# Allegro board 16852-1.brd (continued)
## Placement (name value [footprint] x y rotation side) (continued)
PC5406  SC2D2U10V3KX-L-GP  [C603H36]  51.66 6.13 90 bottom
PC5407  SC2D2U10V3KX-L-GP  [C603H36]  167.89 42.78 90 top
PC5408  SC10U6D3V3MX-GP  [C603H38]  167.89 41.51 90 top
PC5409  SC10U6D3V3MX-GP  [C603H38]  167.26 53.07 90 top
PC5410  SC68P50V2JN-1GP  [C402H22]  161.8 51.55 270 top
PC5411  SC4700P50V2KX-1GP  [C402H22]  169.04 39.74 0 top
PC5412  SC10U6D3V3MX-GP  [C603H38]  167.26 51.8 90 top
PC8501  SCD01U50V2KX-1GP  [C402H22]  211.07 63.61 90 top
PC8502  SCD1U16V2KX-3GP  [C402H22]  208.84 54.98 180 bottom
PC8503  SC1KP50V2KX-1GP  [C402H22]  205.61 57.64 0 bottom
PC8506  SC330P50V2KX-3GP  [C402H22]  206.51 79.66 90 top
PC8507  SCD22U25V3KX-GP  [C603H40]  201.5 68.7 90 top
PC8508  SC1U10V2KX-1GP  [C402H22]  203.58 65.64 270 bottom
PC8509  SC1U10V2KX-1GP  [C402H22]  204.6 69.07 180 top
PC8510  SCD22U25V3KX-GP  [C603H40]  206.76 69.33 0 top
PC8511  SC1KP50V2KX-1GP  [C402H22]  210.57 54.98 180 bottom
PC8512  SC100P50V2JN-3GP  [C402H22]  211.07 66.41 90 top
PC8513  SC1KP50V2KX-1GP  [C402H22]  212.85 62.72 90 top
PC8514  SC180P50V2JN-1GP  [C402H22]  211.46 65.14 180 top
PC8515  SC330P50V2KX-3GP  [C402H22]  212.85 66.41 90 top
PC8516  SC330P50V2KX-3GP  [C402H22]  217.68 60.95 90 top
PC8517  SCD22U10V2KX-1GP  [C402H22]  211.33 57.64 0 top
PC8518  SCD22U10V2KX-1GP  [C402H22]  218.95 56.63 180 bottom
PC8519  SC10U25V5KX-GP  [C805H56]  211.07 93.97 90 bottom
PC8520  SC4D7U25V5KX-GP  [C805H54]  211.07 92.06 90 bottom
PC8521  SCD1U25V2KX-GP  [C402H22]  214.55 84.69 0 bottom
PC8522  SCD022U16V2KX-3GP  [C402H22]  213.74 58.79 180 top
PC8523  SCD1U25V2KX-GP  [C402H22]  214.63 58.79 180 top
PC8524  SC330P50V2KX-3GP  [C402H22]  211.06 62.8 270 top
PC8525  SCD1U25V2KX-GP  [C402H22]  216.92 60.11 90 top
PC8526  SC4D7U25V5KX-GP  [C805H54]  212.22 71.11 180 bottom
PC8527  SC4D7U25V5KX-GP  [C805H54]  210.31 71.11 180 bottom
PC8528  SC10U25V5KX-GP  [C805H56]  212.09 70.85 0 top
PC8529  SC10U25V5KX-GP  [C805H56]  210.19 70.85 0 top
PC8530  SCD1U25V2KX-GP  [C402H22]  215.11 75.45 180 bottom
PC8533  SC330P50V2KX-3GP  [C402H22]  206.51 80.63 90 top
PC8534  SC22U6D3V3MX-1-GP  [C603H40]  190.12 64.5 180 bottom
PC8535  SC22U6D3V3MX-1-GP  [C603H40]  191.77 64.5 0 top
PC8551  SC4D7U25V5KX-GP  [C805H54]  211.07 93.97 270 top
PC8552  SC10U25V5KX-GP  [C805H56]  211.07 92.06 270 top
PC8601  SCD1U16V2KX-3GP  [C402H22]  183.64 65.97 90 bottom
PC8602  SCD47U25V3KX-1GP  [C603H36]  177.22 63.41 90 bottom
PC8603  SCD1U16V2KX-3GP  [C402H22]  181.86 65.97 270 bottom
PC8604  SC22U6D3V5MX-2GP  [C805H58]  182.14 59.52 180 bottom
PC8605  SC22U6D3V5MX-2GP  [C805H58]  183.95 59.52 180 bottom
PC8607  SCD1U16V2KX-3GP  [C402H22]  174.45 61.22 270 bottom
PC8612  SCD22U10V2KX-1GP  [C402H22]  153.49 58.38 270 top
PC8621  SC10U6D3V3MX-GP  [C603H38]  179.6 57.77 270 bottom
PC8622  SC10U6D3V3MX-GP  [C603H38]  179.6 56.37 270 bottom
PC8623  SC1U10V2KX-1GP  [C402H22]  176.45 57.19 90 bottom
PC8624  SC22P50V2JN-4GP  [C402H22]  180.11 61.07 180 bottom
PC8625  SC22U6D3V3MX-1-GP  [C603H40]  169.04 63.23 90 bottom
PC8626  SC22U6D3V3MX-1-GP  [C603H40]  169.04 61.83 90 bottom
PC8634  SC1U10V2KX-1GP  [C402H22]  149.92 54.47 90 top
PC8635  SCD1U16V2KX-3GP  [C402H22]  148.59 54.91 180 top
PC8636  SCD1U16V2KX-3GP  [C402H22]  175.31 76.85 180 top
PC8651  SCD1U25V2KX-L-GP  [C402H22]  208.64 122.03 180 bottom
PC8652  SC10U25V5KX-L-GP  [C805H56]  209.04 124.55 0 bottom
PC8653  SC10U25V3MX-GP  [C603H40]  207.39 124.8 0 bottom
PC8654  SC2D2U10V3KX-L-GP  [C603H36]  200.53 117.16 180 bottom
PC8655  SC1U10V2KX-L1-GP  [C402H22]  202.54 117.1 180 bottom
PC8656  SCD1U25V2KX-L-GP  [C402H22]  202.59 124.85 180 bottom
PC8657  SC22U6D3V5MX-L3-GP  [C805H58]  193.29 125.84 180 top
PC8658  SC22U6D3V5MX-L3-GP  [C805H58]  195.12 125.84 180 top
PC8659  SC22U6D3V5MX-L3-GP  [C805H58]  192.79 120.25 0 top
PC8660  SC22U6D3V5MX-L3-GP  [C805H58]  194.59 120.25 0 top
PC8661  SC22U6D3V5MX-L3-GP  [C805H58]  199.26 126.99 270 bottom
PC8662  SC470P50V2KX-L-GP  [C402H22]  204.34 116.83 0 bottom
PD4301  P6SMB27A-GP  [DO214AAAKH97]  48.59 115.89 90 top
PD4302  LBAV99LT1G-1-GP  [SOT23-2D4-312H44]  33.53 62.34 0 top
PD4303  PESD24VS2UT-GP  [SOT-23-10H44]  28.96 69.2 90 top
PD4304  SMF18AT1G-GP  [SOD123FLAKH40]  231.52 28.69 270 top
PD4402  SD103AWS-2-GP  [SOD323AKH38]  235.71 24.24 270 top
PD4404  1N4148WS-7-F-GP  [SOD323AKH42]  233.12 6.92 0 top
PD4405  SD103AWS-2-GP  [SOD323AKH38]  231.01 24.24 90 top
PD8501  RB551VM-30TE-17-GP  [SOD323-2513AKH36]  205.99 54.34 270 top
PG4401  GAP-CLOSE-PWR-3-GP  [GAP-CLOSE-PWR-3]  239.57 13.12 0 top
PG4402  GAP-CLOSE-PWR-3-GP  [GAP-CLOSE-PWR-3]  66.08 104.58 180 top
PG4403  GAP-CLOSE-PWR-3-GP  [GAP-CLOSE-PWR-3]  66.05 103.1 180 top
PG4404  GAP-CLOSE-PWR-3-GP  [GAP-CLOSE-PWR-3]  223.14 18.02 90 top
PG4405  GAP-CLOSE-PWR-3-GP  [GAP-CLOSE-PWR-3]  221.11 18.02 90 top
PG4406  GAP-CLOSE-PWR-3-GP  [GAP-CLOSE-PWR-3]  224.16 18.02 90 top
PG4407  GAP-CLOSE-PWR-3-GP  [GAP-CLOSE-PWR-3]  222.12 18.02 90 top
PG4409  GAP-CLOSE-PWR-3-GP  [GAP-CLOSE-PWR-3]  239.93 18.02 0 top
PG4410  GAP-CLOSE-PWR-3-GP  [GAP-CLOSE-PWR-3]  239.93 19.04 0 top
PG4411  GAP-CLOSE-PWR-3-GP  [GAP-CLOSE-PWR-3]  241.48 11.97 270 top
PG4412  GAP-CLOSE-PWR-3-GP  [GAP-CLOSE-PWR-3]  225.58 32.37 90 top
PG4413  GAP-CLOSE-PWR-3-GP  [GAP-CLOSE-PWR-3]  227.05 32.37 90 top
PG4414  GAP-CLOSE-PWR-3-GP  [GAP-CLOSE-PWR-3]  239.62 14.13 0 top
PG4415  GAP-CLOSE-PWR-3-GP  [GAP-CLOSE-PWR-3]  239.65 15.15 0 top
PG4416  GAP-CLOSE-PWR-3-GP  [GAP-CLOSE-PWR-3]  237.64 21.83 270 top
PG4417  GAP-CLOSE-PWR-3-GP  [GAP-CLOSE-PWR-3]  236.6 21.83 90 top
PG4501  GAP-CLOSE-PWR-3-GP  [GAP-CLOSE-PWR-3]  27.94 45.83 270 top
PG4502  GAP-CLOSE-PWR-3-GP  [GAP-CLOSE-PWR-3]  28.96 45.83 270 top
PG4503  GAP-CLOSE-PWR-3-GP  [GAP-CLOSE-PWR-3]  26.92 45.83 270 top
PG4504  GAP-CLOSE-PWR-3-GP  [GAP-CLOSE-PWR-3]  42.8 41.39 180 top
PG4505  GAP-CLOSE-PWR-3-GP  [GAP-CLOSE-PWR-3]  42.8 42.4 180 top
PG4506  GAP-CLOSE-PWR-3-GP  [GAP-CLOSE-PWR-3]  29.46 46.92 0 bottom
PG4507  GAP-CLOSE-PWR-3-GP  [GAP-CLOSE-PWR-3]  56.38 40.73 180 top
PG4509  GAP-CLOSE-PWR-3-GP  [GAP-CLOSE-PWR-3]  27.46 29.4 0 bottom
PG4510  GAP-CLOSE-PWR-3-GP  [GAP-CLOSE-PWR-3]  45.72 40.12 270 top
PG4511  GAP-CLOSE-PWR-3-GP  [GAP-CLOSE-PWR-3]  43.69 40.12 270 top
PG4512  GAP-CLOSE-PWR-3-GP  [GAP-CLOSE-PWR-3]  44.7 40.12 270 top
PG4516  GAP-CLOSE-PWR-3-GP  [GAP-CLOSE-PWR-3]  29.18 29.63 270 top
PG4517  GAP-CLOSE-PWR-3-GP  [GAP-CLOSE-PWR-3]  28.27 29.63 270 top
PG4518  GAP-CLOSE-PWR-3-GP  [GAP-CLOSE-PWR-3]  27.36 29.63 270 top
PG4519  GAP-CLOSE-PWR-3-GP  [GAP-CLOSE-PWR-3]  25.53 29.63 270 top
PG4520  GAP-CLOSE-PWR-3-GP  [GAP-CLOSE-PWR-3]  26.44 29.63 270 top
PG4521  GAP-CLOSE-PWR-3-GP  [GAP-CLOSE-PWR-3]  30.1 29.63 270 top
PG4522  GAP-CLOSE-PWR-3-GP  [GAP-CLOSE-PWR-3]  25.91 45.83 270 top
PG4523  GAP-CLOSE-PWR-3-GP  [GAP-CLOSE-PWR-3]  24.61 29.63 270 top
PG4526  GAP-CLOSE-PWR-3-GP  [GAP-CLOSE-PWR-3]  24.89 45.83 270 top
PG4601  GAP-CLOSE-PWR-3-GP  [GAP-CLOSE-PWR-3]  148.59 116.7 0 top
PG4701  GAP-CLOSE-PWR-3-GP  [GAP-CLOSE-PWR-3]  122.05 124.7 90 top
PG4702  GAP-CLOSE-PWR-3-GP  [GAP-CLOSE-PWR-3]  121.13 124.7 90 top
PG4703  GAP-CLOSE-PWR-3-GP  [GAP-CLOSE-PWR-3]  120.19 124.7 90 top
PG4704  GAP-CLOSE-PWR-3-GP  [GAP-CLOSE-PWR-3]  119.28 124.7 90 top
PG4705  GAP-CLOSE-PWR-3-GP  [GAP-CLOSE-PWR-3]  118.26 124.7 90 top
PG4707  GAP-CLOSE-PWR-3-GP  [GAP-CLOSE-PWR-3]  123.95 112.13 90 bottom
PG4708  GAP-CLOSE-PWR-3-GP  [GAP-CLOSE-PWR-3]  123.95 109.84 270 bottom
PG4801  GAP-CLOSE-PWR-3-GP  [GAP-CLOSE-PWR-3]  107.44 123.3 270 bottom
PG4802  GAP-CLOSE-PWR-3-GP  [GAP-CLOSE-PWR-3]  108.46 123.3 270 bottom
PG4803  GAP-CLOSE-PWR-3-GP  [GAP-CLOSE-PWR-3]  109.47 123.3 270 bottom
PG4804  GAP-CLOSE-PWR-3-GP  [GAP-CLOSE-PWR-3]  106.43 123.3 270 top
PG4805  GAP-CLOSE-PWR-3-GP  [GAP-CLOSE-PWR-3]  107.44 123.3 270 top
PG4808  GAP-CLOSE-PWR-3-GP  [GAP-CLOSE-PWR-3]  113.59 108.19 90 bottom
PG4809  GAP-CLOSE-PWR-3-GP  [GAP-CLOSE-PWR-3]  113.59 106.41 270 bottom
PG5001  -  [GAP-CLOSE-PWR]  131.44 125.26 270 bottom
PG5002  -  [GAP-CLOSE-PWR]  132.46 125.26 270 bottom
PG5021  GAP-CLOSE-PWR-3-GP  [GAP-CLOSE-PWR-3]  135.42 110.94 90 bottom
PG5022  GAP-CLOSE-PWR-3-GP  [GAP-CLOSE-PWR-3]  135.42 108.65 270 bottom
PG5105  GAP-CLOSE-PWR-3-GP  [GAP-CLOSE-PWR-3]  58.32 70.45 0 top
PG5106  GAP-CLOSE-PWR-3-GP  [GAP-CLOSE-PWR-3]  67.35 54.06 270 top
PG5107  GAP-CLOSE-PWR-3-GP  [GAP-CLOSE-PWR-3]  68.36 54.06 270 top
PG5108  GAP-CLOSE-PWR-3-GP  [GAP-CLOSE-PWR-3]  69.38 54.06 270 top
PG5109  GAP-CLOSE-PWR-3-GP  [GAP-CLOSE-PWR-3]  71.41 54.06 270 top
PG5110  GAP-CLOSE-PWR-3-GP  [GAP-CLOSE-PWR-3]  58.32 71.46 0 top
PG5111  GAP-CLOSE-PWR-3-GP  [GAP-CLOSE-PWR-3]  70.39 54.06 270 top
PG5112  GAP-CLOSE-PWR-3-GP  [GAP-CLOSE-PWR-3]  58.57 62.28 90 top
PG5113  GAP-CLOSE-PWR-3-GP  [GAP-CLOSE-PWR-3]  66.55 56.12 0 top
PG5114  GAP-CLOSE-PWR-3-GP  [GAP-CLOSE-PWR-3]  58.2 67.05 0 top
PG5120  GAP-CLOSE-PWR-3-GP  [GAP-CLOSE-PWR-3]  59.18 52.49 270 top
PG5121  GAP-CLOSE-PWR-3-GP  [GAP-CLOSE-PWR-3]  60.2 52.49 270 top
PG5301  GAP-CLOSE-PWR-3-GP  [GAP-CLOSE-PWR-3]  38.62 18.56 270 top
PG5302  GAP-CLOSE-PWR-3-GP  [GAP-CLOSE-PWR-3]  37.71 18.56 270 top
PG5303  GAP-CLOSE-PWR-3-GP  [GAP-CLOSE-PWR-3]  34 18.56 270 top
PG5304  GAP-CLOSE-PWR-3-GP  [GAP-CLOSE-PWR-3]  36.79 18.56 270 top
PG5305  GAP-CLOSE-PWR-3-GP  [GAP-CLOSE-PWR-3]  35.88 18.56 270 top
PG5306  GAP-CLOSE-PWR-3-GP  [GAP-CLOSE-PWR-3]  34.97 18.56 270 top
PG5307  GAP-CLOSE-PWR-3-GP  [GAP-CLOSE-PWR-3]  47.12 35.55 270 top
PG5308  GAP-CLOSE-PWR-3-GP  [GAP-CLOSE-PWR-3]  49.15 35.55 270 top
PG5309  GAP-CLOSE-PWR-3-GP  [GAP-CLOSE-PWR-3]  48.13 35.55 270 top
PG5310  GAP-CLOSE-PWR-3-GP  [GAP-CLOSE-PWR-3]  41.4 19.8 180 top
PG5311  GAP-CLOSE-PWR-3-GP  [GAP-CLOSE-PWR-3]  39.54 18.56 270 top
PG5312  GAP-CLOSE-PWR-3-GP  [GAP-CLOSE-PWR-3]  40.48 18.56 270 top
PG5401  -  [GAP-CLOSE-PWR]  164.63 53.73 90 top
PG5402  -  [GAP-CLOSE-PWR]  165.63 53.73 90 top
PG5404  -  [GAP-CLOSE-PWR]  64.9 5.09 0 bottom
PG5405  -  [GAP-CLOSE-PWR]  64.9 6.11 0 bottom
PG8501  -  [GAP-CLOSE-PWR]  212.72 96.12 270 bottom
PG8502  -  [GAP-CLOSE-PWR]  211.71 96.12 270 bottom
PG8503  -  [GAP-CLOSE-PWR]  210.69 96.12 270 bottom
PG8504  -  [GAP-CLOSE-PWR]  212.72 96.12 270 top
PG8505  -  [GAP-CLOSE-PWR]  211.71 96.12 270 top
PG8506  -  [GAP-CLOSE-PWR]  210.69 96.12 270 top
PG8507  GAP-CLOSE-PWR-3-GP  [GAP-CLOSE-PWR-3]  204.61 75.07 0 bottom
PG8508  GAP-CLOSE-PWR-3-GP  [GAP-CLOSE-PWR-3]  202.13 75.04 180 bottom
PG8509  GAP-CLOSE-PWR-3-GP  [GAP-CLOSE-PWR-3]  204.47 82.74 0 bottom
PG8510  GAP-CLOSE-PWR-3-GP  [GAP-CLOSE-PWR-3]  202.1 82.71 180 bottom
PG8511  -  [GAP-CLOSE-PWR]  215.75 71.97 180 top
PG8512  -  [GAP-CLOSE-PWR]  215.75 72.98 180 top
PG8513  -  [GAP-CLOSE-PWR]  215.75 74 180 top
PG8514  -  [GAP-CLOSE-PWR]  215.77 71.99 180 bottom
PG8515  -  [GAP-CLOSE-PWR]  215.77 73.01 180 bottom
PG8516  -  [GAP-CLOSE-PWR]  215.77 74.03 180 bottom
PG8601  -  [GAP-CLOSE-PWR]  176.91 55.87 90 bottom
PG8602  -  [GAP-CLOSE-PWR]  177.93 55.87 90 bottom
PG8603  -  [GAP-CLOSE-PWR]  171.27 64.6 90 bottom
PG8604  -  [GAP-CLOSE-PWR]  170.18 64.6 90 bottom
PG8651  GAP-CLOSE-PWR-3-GP  [GAP-CLOSE-PWR-3]  209.55 122.03 90 bottom
PG8652  GAP-CLOSE-PWR-3-GP  [GAP-CLOSE-PWR-3]  210.57 122.03 90 bottom
PG8653  GAP-CLOSE-PWR-3-GP  [GAP-CLOSE-PWR-3]  196.72 120.76 180 bottom
PG8655  GAP-CLOSE-PWR-3-GP  [GAP-CLOSE-PWR-3]  209.04 117.46 180 bottom
PG8656  GAP-CLOSE-PWR-3-GP  [GAP-CLOSE-PWR-3]  192.56 119.82 270 bottom
PG8657  GAP-CLOSE-PWR-3-GP  [GAP-CLOSE-PWR-3]  191.77 122.08 180 bottom
PG8658  GAP-CLOSE-PWR-3-GP  [GAP-CLOSE-PWR-3]  191.77 121.12 180 bottom
PG8660  GAP-CLOSE-PWR-3-GP  [GAP-CLOSE-PWR-3]  191.74 124.27 180 bottom
PL4401  COIL-4D7UH-33-GP  [L7066-1830-UH119]  222.5 33.01 0 bottom
PL4501  IND-2D2UH-46-GP-U1  [L7066-1830-UH119]  33.94 43.36 270 bottom
PL4502  IND-2D2UH-46-GP-U1  [L7066-1830-UH119]  33.78 33.77 90 bottom
PL4701  COIL-D15UH-2-GP  [L7366-1930H158]  123.95 110.98 180 bottom
PL4801  COIL-D15UH-2-GP  [L7366-1930H158]  113.03 107.33 180 bottom
PL5001  IND-D47UH-22-GP-U  [L7066-1830-UH119]  135.42 109.79 180 bottom
PL5101  COIL-1UH-34-GP-U1  [L7066-1830-UH119]  70 64.1 180 bottom
PL5301  COIL-1UH-34-GP-U1  [L7066-1830-UH119]  34.58 25.37 180 bottom
PL8501  IND-D33UH-7-GP-U  [L7066-1830-UH119]  203.33 74.97 90 bottom
PL8502  IND-D33UH-7-GP-U  [L7066-1830-UH119]  203.33 82.71 90 bottom
PL8601  IND-1UH-300-GP  [L2520-D620H48]  171.22 58.89 90 bottom
PL8651  COIL-1UH-34-GP-U1  [L7066-1830-UH119]  197.61 122.16 90 bottom
PQ4301  DMN5L06K-7-GP  [SOT23DGS2D4H48]  32.89 66.41 0 top
PQ4302  LMBT3904LT1G-GP  [SOT23CBE2D4H44]  29.72 62.6 180 top
PQ4304  LMUN5212T1G-GP  [SOT323CBE2D2H40]  57.96 103.41 0 top
PQ4305  LTA024EUBFS8TL-GP  [SC70-2D2-312H44]  61.11 103.39 0 top
PQ4306  2N7002KDW-GP  [SOT-363H44]  53.39 102.37 0 top
PQ4402  2N7002KDW-GP  [SOT-363H44]  74.75 108.54 180 top
PQ4403  2N7002K-2-GP  [SOT23DGS2D4H44]  239.65 25.89 90 top
PQ4405  2N7002KDW-GP  [SOT-363H44]  245.03 14.51 180 top
PQ4408  LMBT3906LT1G-1-GP  [SOT23CBE2D4H44]  236.14 6.67 0 top
PQ8501  2N7002KDW-GP  [SOT-363H44]  209.8 52.94 270 top
PQ8604  2N7002KDW-GP  [SOT-363H44]  179.96 63.74 180 bottom
PQ8607  DMP2130L-7-GP  [SOT23DGS2D4H48]  148.15 52.16 180 top
PQ8608  2N7002K-2-GP  [SOT23DGS2D4H44]  152.58 55.94 180 top
PQ8609  PJA3419-GP  [SOT23DGS2D4H44]  183.26 63.49 0 bottom
PR4302  15KR2F-GP  [R402H16]  29.97 65.01 270 top
PR4303  10KR2J-3-GP  [R402H16]  29.07 60.29 90 top
PR4304  2K2R2J-2-GP  [R402H16]  35.94 62.34 180 top
PR4305  33R2J-2-GP  [R402H16]  35.18 64.63 0 top
PR4306  33R2J-2-GP  [R402H16]  32.51 68.82 90 top
PR4307  240KR3-GP  [R603H22]  60.45 107.17 0 top
PR4308  47KR3J-L-GP  [R603H22]  62.46 106.03 90 top
PR4309  100KR2J-1-GP  [R402H16]  30.48 66.41 0 top
PR4312  100KR2J-1-GP  [R402H16]  50.33 101.09 90 top
PR4313  100KR2J-1-GP  [R402H16]  50.3 100.17 270 top
PR4314  3K3R6J-GP  [R1206H28]  49.15 112.51 270 top
PR4317  0R0603-PAD-1-GP-U  [0R0603-PAD-U]  30.48 71.99 90 bottom
PR4402  D01R3721F-GP-U  [R3720H40]  68.57 103.84 0 top
PR4403  100KR2J-1-GP  [R402H16]  71.6 105.4 180 top
PR4404  0R2J-2-GP  [R402H16]  231.91 11.34 90 top
PR4405  3KR5J-GP  [R805H24]  72.21 109.81 0 top
PR4406  10KR2F-2-GP  [R402H16]  72.9 105.78 270 top
PR4407  10R2J-2-GP  [R402H14]  229.29 14.72 90 top
PR4408  309KR2F-GP  [R402H16]  239.7 11.59 180 top
PR4409  47KR2F-GP  [R402H16]  238.07 11.59 0 top
PR4410  4K02R2F-GP  [R402H16]  234.37 11.09 180 top
PR4411  3K3R2J-3-GP  [R402H16]  241.2 17.64 180 top
PR4412  3K3R2J-3-GP  [R402H16]  241.2 19.44 0 top
PR4413  100KR2F-L1-GP  [R402H16]  244.4 12.1 90 top
PR4414  10R2F-L-GP  [R402H14]  234.72 21.8 90 top
PR4415  D01R3721F-GP-U  [R3720H40]  226.31 34.78 90 top
PR4416  0R0402-PAD-2-GP  [0R0402-PAD-1]  235.26 11.09 180 top
PR4417  10R2F-L-GP  [R402H14]  232.33 21.55 180 top
PR4418  0R0402-PAD-2-GP  [0R0402-PAD-1]  239.85 16.7 270 top
PR4419  10R2F-L-GP  [R402H14]  233.22 21.55 180 top
PR4420  100KR2J-1-GP  [R402H16]  230.89 21.12 90 top
PR4421  59KR2F-GP  [R402H16]  238.61 20.99 0 top
PR4422  20KR3J-1-GP  [R603H22]  236.85 26.78 180 top
PR4423  59KR2F-GP  [R402H16]  230.89 21.96 270 top
PR4424  10KR2F-2-GP  [R402H16]  239.5 20.99 180 top
PR4425  30KR2F-GP  [R402H16]  241.94 15.15 90 top
PR4430  470KR2F-GP  [R402H16]  237.74 32.24 0 bottom
PR4431  100KR2J-1-GP  [R402H16]  241.22 9.94 90 top
PR4432  120KR2J-GP  [R402H16]  236.65 12.36 90 top
PR4433  1MR2J-1-GP  [R402H16]  241.22 10.83 270 top
PR4435  100KR2J-1-GP  [R402H16]  236.14 11.09 180 top
PR4450  10KR2F-2-GP  [R402H16]  246.18 12.1 90 top
PR4451  680KR2F-GP  [R402H16]  238.71 9.38 0 top
PR4455  0R0402-PAD-2-GP  [0R0402-PAD-1]  242.65 16.19 270 top
PR4458  0R0402-PAD-2-GP  [0R0402-PAD-1]  231.57 6.39 0 top
PR4462  0R0402-PAD-2-GP  [0R0402-PAD-1]  237.41 9.82 90 top
PR4463  0R2J-2-GP  [R402H16]  237.03 11.09 180 top
PR4502  0R0402-PAD-1-GP  [0R0402-PAD]  53.92 47.43 0 top
PR4503  1D5R3F-GP  [R603H22]  49.8 47.82 0 top
PR4505  165KR2F-L-GP  [R402H16]  56.01 46.9 90 top
PR4506  0R2J-2-GP  [R402H16]  57.81 45.64 0 top
PR4507  0R0402-PAD-1-GP  [0R0402-PAD]  53.85 38.54 0 top
PR4508  100KR2J-1-GP  [R402H16]  52.27 47.52 0 top
PR4509  1D5R3F-GP  [R603H22]  50.62 38.42 0 top
PR4510  130KR2F-L-GP  [R402H16]  55.24 38.59 0 top
PR4512  0R2J-2-GP  [R402H16]  58.22 38.57 270 top
PR4514  15KR2F-GP  [R402H16]  58.22 39.41 270 top
PR4515  10KR2F-2-GP  [R402H16]  56.52 39.86 90 top
PR4516  6K65R2F-GP  [R402H16]  56.05 45.03 270 top
PR4517  10KR2F-2-GP  [R402H16]  56.03 45.95 90 top
PR4601  1KR2F-3-GP  [R402H16]  142.11 109.28 270 bottom
PR4602  1K5R2F-2-GP  [R402H16]  154.38 114.39 270 bottom
PR4603  1KR2F-3-GP  [R402H16]  144.7 107.65 0 bottom
PR4604  0R0402-PAD-2-GP  [0R0402-PAD-1]  154.81 112.43 90 bottom
PR4605  825R2F-GP  [R402H16]  152.27 112.51 90 bottom
PR4606  NTC-100K-11-GP-U  [NTC-402H24-U]  139.83 108.7 0 bottom
PR4607  0R0402-PAD-2-GP  [0R0402-PAD-1]  154.81 111.62 90 bottom
PR4608  2K94R2F-GP  [R402H16]  152.27 110.73 90 bottom
PR4609  14K3R2F-GP  [R402H16]  154.31 115.78 180 bottom
PR4611  34KR2F-GP  [R402H16]  151.97 114.23 270 bottom
PR4612  8K06R3F-AS-GP  [R603H22]  153.21 116.39 180 bottom
PR4613  115KR2F-GP  [R402H16]  149.48 114.67 270 top
PR4614  10KR2F-2-GP  [R402H16]  152.45 120.05 90 bottom
PR4616  2K49R2F-GP  [R402H16]  153.54 110.22 180 bottom
PR4617  0R0402-PAD-2-GP  [0R0402-PAD-1]  152.78 110.22 180 top
PR4618  0R0402-PAD-2-GP  [0R0402-PAD-1]  152.78 107.81 270 top
PR4619  1KR2F-3-GP  [R402H16]  148.72 108.52 90 bottom
PR4621  45D3R2F-L-GP  [R402H16]  150.19 121.88 180 bottom
PR4622  75R2F-2-GP  [R402H16]  149.35 121.91 0 top
PR4623  100R2F-L1-GP-U  [R402H14]  148.51 121.93 180 bottom
PR4624  1KR2F-3-GP  [R402H16]  148.46 121.91 0 top
PR4625  37D4R2F-GP  [R402H16]  148.16 106.83 0 top
PR4626  1KR2F-3-GP  [R402H16]  147.65 108.1 270 top
PR4627  8K06R3F-AS-GP  [R603H22]  147.44 122.59 0 bottom
PR4628  95K3R2F-GP  [R402H16]  146.94 116.95 0 top
PR4629  14KR2F-GP  [R402H16]  146.3 122.34 0 bottom
PR4630  0R0402-PAD-2-GP  [0R0402-PAD-1]  151.13 119.62 0 bottom
PR4631  4K75R2F-1-GP  [R402H16]  146.89 106.32 270 top
PR4632  24K9R2F-L-GP  [R402H16]  147.07 111.11 0 top
PR4633  NTC-100K-11-GP-U  [NTC-402H24-U]  128.4 112.63 0 bottom
PR4634  NTC-220K-GP-U  [NTC-402H22-U]  118.24 111.41 180 bottom
PR4635  49K9R2F-L-GP  [R402H16]  145.09 119.33 180 top
PR4636  2K49R2F-GP  [R402H16]  144.66 120.72 90 top
PR4637  57K6R3F-2-GP  [R603H22]  144.02 104.86 270 bottom
PR4638  200KR2F-L-GP  [R402H16]  145.62 105.94 0 bottom
PR4639  75KR2F-GP  [R402H16]  146.89 106.35 270 bottom
PR4640  12K4R2F-GP  [R402H16]  147.65 107.2 270 bottom
PR4644  422R2F-2-GP  [R402H16]  144.02 119.62 0 bottom
PR4645  0R0402-PAD-2-GP  [0R0402-PAD-1]  143 120.25 180 bottom
PR4646  10R2F-L-GP  [R402H14]  144.46 106.89 0 top
PR4647  3K83R2F-GP  [R402H16]  142.22 117.75 0 bottom
PR4648  0R0402-PAD-2-GP  [0R0402-PAD-1]  142.19 120.25 180 bottom
PR4649  2K49R2F-GP  [R402H16]  141.4 117.75 0 bottom
PR4650  0R0402-PAD-2-GP  [0R0402-PAD-1]  140.44 112.96 270 bottom
PR4651  4K87R2F-GP  [R402H16]  143.62 106.9 180 top
PR4652  21K5R2F-GP  [R402H16]  140.06 111.69 180 bottom
PR4653  NTC-100K-11-GP-U  [NTC-402H24-U]  128.27 120.89 270 bottom
PR4655  0R0402-PAD-2-GP  [0R0402-PAD-1]  143.87 107.64 0 bottom
PR4656  NTC-100K-11-GP-U  [NTC-402H24-U]  116.33 116.01 270 bottom
PR4657  2D2R2F-GP  [R402H16]  141.68 110.58 0 bottom
PR4658  100KR2F-L1-GP  [R402H16]  143.51 114.54 90 top
PR4659  24KR2F-GP  [R402H16]  143.51 112.76 90 top
PR4660  15K8R2F-GP  [R402H16]  143.51 115.43 90 top
PR4661  7K68R2F-GP  [R402H16]  143.04 107.64 0 bottom
PR4662  48D7KR2F-GP  [R402H16]  143.51 113.65 90 top
PR4663  10KR2F-2-GP  [R402H16]  142.88 116.44 90 top
PR4664  24KR2F-GP  [R402H16]  143.51 111.87 90 top
PR4665  49D9R2F-GP  [R402H16]  150.24 119.62 180 bottom
PR4666  0R0402-PAD-1-GP  [0R0402-PAD]  149.35 119.62 0 bottom
PR4667  10R2F-L-GP  [R402H14]  148.46 119.62 180 bottom
PR4668  100R2F-L1-GP-U  [R402H14]  147.57 119.62 0 bottom
PR4669  75R2F-2-GP  [R402H16]  147.57 121.91 0 top
PR4670  0R0402-PAD-2-GP  [0R0402-PAD-1]  152.4 118.98 270 bottom
PR4671  0R0402-PAD-2-GP  [0R0402-PAD-1]  149.73 108.19 180 top
PR4701  3D9R3-GP  [R603H22]  126.8 123.84 0 bottom
PR4702  2D2R2F-GP  [R402H16]  128.97 117.44 270 bottom
PR4703  2D2R5F-2-GP  [R805H24]  119.11 114.16 0 bottom
PR4704  0R0402-PAD-2-GP  [0R0402-PAD-1]  128.78 119.24 90 bottom
PR4802  3D9R3-GP  [R603H22]  112.93 119.64 0 bottom
PR4803  2D2R2F-GP  [R402H16]  116.41 113.47 270 bottom
PR4804  2D2R5F-2-GP  [R805H24]  107.95 110.35 0 bottom
PR4808  0R0402-PAD-2-GP  [0R0402-PAD-1]  116.41 115.1 90 bottom
PR5013  2D2R3-1-U-GP  [R603H22]  143.7 123.99 0 bottom
PR5014  2D2R5F-2-GP  [R805H24]  135.51 116.19 0 bottom
PR5101  20KR2F-L-GP  [R402H16]  61.88 63.98 0 top
PR5102  0R0603-PAD-1-GP-U  [0R0603-PAD-U]  65.66 72.45 90 top
PR5103  0R2J-2-GP  [R402H16]  60.12 64 0 top
PR5104  100KR2J-1-GP  [R402H16]  58.57 66.14 90 top
PR5105  1MR2J-1-GP  [R402H16]  58.63 65.3 270 top
PR5106  0R2J-2-GP  [R402H16]  61.01 64 180 top
PR5107  20KR2F-L-GP  [R402H16]  63.58 63.95 180 top
PR5114  -  [0R0402-PAD]  63.77 45.84 180 top
PR5118  -  [0R0402-PAD]  65.41 47.44 0 top
PR5125  -  [0R0402-PAD]  60.32 46.86 180 top
PR5126  0R2J-2-GP  [R402H16]  61.16 46.83 180 top
PR5301  95K3R2F-GP  [R402H16]  47.42 31.1 180 top
PR5302  2K55R2F-GP  [R402H16]  50.29 30.21 270 top
PR5303  100KR2F-L3-GP  [R402H16]  49.28 28.69 180 top
PR5304  10KR2F-2-GP  [R402H16]  48.13 29.07 0 top
PR5305  0R0402-PAD-1-GP  [0R0402-PAD]  48.77 26.53 270 top
PR5306  0R0402-PAD-1-GP  [0R0402-PAD]  202.31 24.5 0 bottom
PR5307  100KR2J-1-GP  [R402H16]  47.75 22.95 90 top
PR5308  0R2J-2-GP  [R402H16]  48.77 27.42 270 top
PR5403  21K5R2F-GP  [R402H16]  63.6 4.71 180 bottom
PR5404  10KR2F-2-GP  [R402H16]  63.09 3.01 180 bottom
PR5405  0R0402-PAD-1-GP  [0R0402-PAD]  54.1 9.13 270 bottom
PR5407  10KR2F-2-GP  [R402H16]  55.85 9.1 270 bottom
PR5408  47KR2J-2-GP  [R402H16]  168.15 39.74 0 top
PR5409  100KR2F-L1-GP  [R402H16]  160.15 42.66 90 top
PR5410  16K5R2F-2-GP  [R402H16]  161.8 52.44 270 top
PR5411  13KR2F-GP  [R402H16]  160.02 51.55 270 top
PR5412  0R2J-2-GP  [R402H16]  169.93 40.75 0 top
PR5413  0R0402-PAD-1-GP  [0R0402-PAD]  167.26 39.74 180 top
PR5414  0R0402-PAD-2-GP  [0R0402-PAD-1]  160.15 41.77 90 top
PR5415  10KR2J-3-GP  [R402H16]  53.34 3.29 270 bottom
PR8501  10KR2J-3-GP  [R402H16]  199.77 63.87 90 top
PR8502  10KR2J-3-GP  [R402H16]  199.77 64.76 90 top
PR8503  10KR2F-2-GP  [R402H16]  205.1 52.44 90 top
PR8505  0R0402-PAD-1-GP  [0R0402-PAD]  206.5 57.9 180 top
PR8506  100KR2F-L1-GP  [R402H16]  202.31 61.96 180 bottom
PR8507  2D2R3-1-U-GP  [R603H22]  201.04 66.87 180 top
PR8508  100KR2F-L1-GP  [R402H16]  203.2 61.96 180 bottom
PR8509  0R0402-PAD-1-GP  [0R0402-PAD]  200.91 59.68 270 bottom
PR8510  1R2F-GP  [R402H16]  203.71 69.07 0 top
PR8511  0R0402-PAD-1-GP  [0R0402-PAD]  200.91 58.79 270 bottom
PR8512  0R0402-PAD-1-GP  [0R0402-PAD]  200.91 57.9 270 bottom
PR8513  0R0402-PAD-1-GP  [0R0402-PAD]  207.39 57.9 180 top
PR8514  0R0402-PAD-1-GP  [0R0402-PAD]  208.28 57.9 180 top
PR8515  2D2R3-1-U-GP  [R603H22]  208.03 69.33 180 top
PR8516  133KR2F-GP  [R402H16]  209.68 54.98 180 bottom
PR8517  3K65R2F-1-GP  [R402H16]  216.28 56.09 270 top
PR8518  1KR2J-1-GP  [R402H16]  207.14 55.1 270 bottom
PR8519  10KR2F-2-GP  [R402H16]  218.06 56.63 180 bottom
PR8520  0R0402-PAD-1-GP  [0R0402-PAD]  207.14 54.21 90 bottom
PR8521  1R2F-GP  [R402H16]  219.84 56.63 180 bottom
PR8522  10KR2J-3-GP  [R402H16]  214.02 56.65 0 top
PR8523  301R2F-GP  [R402H16]  212.85 64.63 270 top
PR8524  100KR2F-L1-GP  [R402H16]  210.44 57.64 180 top
PR8525  1KR2F-3-GP  [R402H16]  212.85 61.83 270 top
PR8526  33KR2F-GP  [R402H16]  214.63 61.83 270 top
PR8527  2KR2F-3-GP  [R402H16]  215.9 60.95 90 top
PR8528  32K4R2F-1-GP  [R402H16]  212.85 65.52 90 top
PR8529  2K61R2F-1-GP  [R402H16]  216.92 58.15 90 top
PR8530  0R0402-PAD-1-GP  [0R0402-PAD]  212.85 63.61 90 top
PR8531  10R2J-2-GP  [R402H14]  180.84 79.33 270 top
PR8532  11KR2F-L-GP  [R402H16]  215.52 58.79 180 top
PR8533  NTC-10K-29-GP-U  [NTC-402H22-U]  217.04 59.17 270 top
PR8534  0R0402-PAD-1-GP  [0R0402-PAD]  212.85 60.95 90 top
PR8535  10R2J-2-GP  [R402H14]  181.04 77.07 90 top
PR8536  1K58R2F-GP  [R402H16]  212.85 60.06 270 top
PR8537  3K65R2F-1-GP  [R402H16]  215.11 54.77 270 top
PR8538  10KR2F-2-GP  [R402H16]  213.11 56.63 0 top
PR8539  100KR2J-1-GP  [R402H16]  212.6 53.07 90 top
PR8540  1R2F-GP  [R402H16]  218.74 59.04 180 bottom
PR8541  2D2R3J-2-GP  [R603H22]  204.97 78.9 180 top
PR8542  2D2R3J-2-GP  [R603H22]  204.97 81.32 0 top
PR8543  10KR2J-3-GP  [R402H16]  219.58 58.41 0 bottom
PR8544  0R0402-PAD-1-GP  [0R0402-PAD]  207.98 57.19 90 bottom
PR8545  100R2J-2-GP  [R402H14]  205.1 51.42 270 top
PR8546  0R2J-2-GP  [R402H16]  205.61 57.64 180 top
PR8601  0R2J-2-GP  [R402H16]  185.27 60.54 180 bottom
PR8603  1KR2J-1-GP  [R402H16]  155.17 58.58 270 top
PR8606  100KR2J-1-GP  [R402H16]  181.86 66.86 270 bottom
PR8609  75R2F-2-GP  [R402H16]  177.6 61.86 180 bottom
PR8619  100KR2J-1-GP  [R402H16]  183.64 66.86 90 bottom
PR8621  0R0402-PAD-1-GP  [0R0402-PAD]  174.45 62.11 90 bottom
PR8622  30K1R2F-L-GP  [R402H16]  179.3 61.07 180 bottom
PR8623  51K1R2F-GP  [R402H16]  178.49 61.07 0 bottom
PR8624  10KR2J-3-GP  [R402H16]  179.2 59.68 90 bottom
PR8625  10KR2J-3-GP  [R402H16]  174.5 62.98 270 bottom
PR8650  10KR2J-3-GP  [R402H16]  149.48 55.8 180 top
PR8651  2K2R2J-2-GP  [R402H16]  150.37 55.8 0 top
PR8661  10KR2J-3-GP  [R402H16]  176.71 61.86 0 bottom
PR8671  0R0402-PAD-1-GP  [0R0402-PAD]  206.12 117.08 180 bottom
PR8672  1MR2J-1-GP  [R402H16]  207.9 117.08 180 bottom
PR8673  100KR2J-1-GP  [R402H16]  208.46 118.37 90 bottom
PR8674  0R0603-PAD-1-GP-U  [0R0603-PAD-U]  203.63 124.75 0 bottom
PR8675  24K9R2F-L-GP  [R402H16]  203.45 116.83 0 bottom
PR8676  16K5R2F-2-GP  [R402H16]  205.16 116.83 180 bottom
PR8677  0R2J-2-GP  [R402H16]  207.01 117.08 180 bottom
PT4501  ST150U6D3VDM-28-GP  [CT7343H83]  26.91 42.73 180 bottom
PT4502  ST150U6D3VDM-28-GP  [CT7343H83]  24.26 33.39 0 bottom
PT4702  ST330U2D5VBM-1-GP  [CT3528H79]  118.49 107.05 0 bottom
PT4703  SE33U25VM-11-GP  [CT7343H83]  156.34 121.32 180 bottom
PT4704  SE33U25VM-11-GP  [CT7343H83]  117.42 121.27 180 bottom
PT4801  ST330U2D5VBM-1-GP  [CT3528H79]  107.19 104.89 0 bottom
PT8501  SE330U2VDM-4-GP  [CT7343H83]  196.29 72.5 180 bottom
PT8506  SE330U2VDM-4-GP  [CT7343H83]  196.29 81.87 0 bottom
PT8507  SE330U2VDM-4-GP  [CT7343H83]  196.44 63.08 180 bottom
PU4301  AON7403-GP-U  [PPAK-8P-3232H36]  64.82 108.85 270 top
PU4401  BQ24786RUYR-GP  [QFN28-G2D7H32]  233.17 17 180 top
PU4402  AON7403-GP-U  [PPAK-8P-3232H36]  68.93 109.31 0 top
PU4403  AON7403-GP-U  [PPAK-8P-3232H36]  222.5 35.16 270 top
PU4404  AON7410-GP  [PPAK-8P-3232H36]  221.87 25.64 180 top
PU4405  AON7410-GP  [PPAK-8P-3232H36]  226.31 27.16 0 top
PU4501  RT6575DGQW-GP  [QFN20-G1D75H32]  52.14 42.84 270 top
PU4502  AON7410-GP  [PPAK-8P-3232H36]  38.76 41.2 270 top
PU4503  AON7410-GP  [PPAK-8P-3232H36]  37.26 45.63 90 top
PU4504  AON7410-GP  [PPAK-8P-3232H36]  38.75 36.73 270 top
PU4505  AON7410-GP  [PPAK-8P-3232H36]  37.3 32.32 90 top
PU4601  NCP81218MNTXG-GP  [LFQFN48J6-G4D6H40]  146.43 113.78 0 bottom
PU4701  NCP81381MNTXG-1-GP  [QFN36J4060-G2554H48]  123.57 118.6 90 bottom
PU4801  NCP81381MNTXG-1-GP  [QFN36J4060-G2554H48]  111.25 115.05 90 bottom
PU5001  NCP81253MNTBG-1-GP  [LFDFN8G2-G1309H40]  140.72 122.79 90 bottom
PU5002  AON7410-GP  [PPAK-8P-3232H36]  132.33 117.84 180 bottom
PU5003  AON7410-GP  [PPAK-8P-3232H36]  138.68 116.32 0 bottom
PU5101  SY8286RAC-GP  [QFN20Z3-G1D1H36]  62.23 67.71 0 top
PU5102  APL5338XAI-TRG-GP  [MSOP10-G2D5H44]  62.83 51.59 180 top
PU5301  AOZ2261QI-10-GP-U  [QFN22G4-G2PH42]  43.78 28.45 270 top
PU5401  RT9025-25ZSP-2-GP  [SOIC8-G2D3H70]  161.69 47.1 0 top
PU5402  RT9025-25ZSP-2-GP  [SOIC8-G2D3H70]  58.14 4.66 90 bottom
PU8501  ISL62771HRTZ-GP-U  [QFN40-G3D5H32]  205.23 63.49 180 top
PU8502  FDMS3600-02-RJK0215-COLAY-GP  [PPAK-8P-G5324H44-COLAY]  211.15 76.6 0 top
PU8503  FDMS3600-02-RJK0215-COLAY-GP  [PPAK-8P-G5324H44-COLAY]  211.15 76.6 180 bottom
PU8504  FDMS3600-02-RJK0215-COLAY-GP  [PPAK-8P-G5324H44-COLAY]  211.02 86.21 0 bottom
PU8505  FDMS3600-02-RJK0215-COLAY-GP  [PPAK-8P-G5324H44-COLAY]  211.02 86.21 180 top
PU8601  SYW232DFC-GP  [DFN8G2-G1711H26]  176.15 59.17 90 bottom
PU8651  SY8286RAC-GP  [QFN20Z3-G1D1H36]  204.85 121.02 180 bottom
PWR1  ACES-CON4-88-GP  [50524-00401-001]  273.9 33.5 90 top
PWSW2  SW-TACT-130-GP-U  [TJE-533-S-V-T-R-744]  217.93 52.44 90 bottom
Q501  DMN5L06K-7-GP  [SOT23DGS2D4H48]  80.84 52.24 90 top
Q502  2N7002K-2-GP  [SOT23DGS2D4H44]  77.09 52.82 0 top
Q1701  2N7002KDW-GP  [SOT-363H44]  154.81 68.69 90 bottom
Q1702  2N7002KDW-GP  [SOT-363H44]  155.3 72.1 270 bottom
Q1801  2N7002KDW-GP  [SOT-363H44]  143.64 58.15 270 bottom
Q1802  2N7002K-2-GP  [SOT23DGS2D4H44]  138.56 46.98 0 top
Q2401  2N7002K-2-GP  [SOT23DGS2D4H44]  225.55 11.92 90 top
Q2408  2N7002K-2-GP  [SOT23DGS2D4H44]  203.45 28.94 90 bottom
Q2417  2N7002KDW-GP  [SOT-363H44]  200.91 10.3 180 top
Q2418  2N7002KDW-GP  [SOT-363H44]  197.79 10.3 180 top
Q2505  2N7002K-2-GP  [SOT23DGS2D4H44]  227.2 43.42 180 top
Q2601  2N7002KDW-GP  [SOT-363H44]  75.51 92.26 0 bottom
Q2602  2N7002K-2-GP  [SOT23DGS2D4H44]  73.15 87.46 0 bottom
Q2603  LMBT3904LT1G-GP  [SOT23CBE2D4H44]  195.61 28.81 180 bottom
Q2604  2N7002KDW-GP  [SOT-363H44]  222.4 5.29 270 bottom
Q2606  2N7002K-2-GP  [SOT23DGS2D4H44]  206.63 102.4 0 bottom
Q2701  DMP2130L-7-GP  [SOT23DGS2D4H48]  35.61 5.45 0 bottom
Q2702  2N7002K-2-GP  [SOT23DGS2D4H44]  39.29 5.45 0 bottom
Q3101  2N7002K-2-GP  [SOT23DGS2D4H44]  31.62 96.25 90 top
Q3104  DMP2130L-7-GP  [SOT23DGS2D4H48]  38.48 96.51 270 top
Q4001  2N7002KDW-GP  [SOT-363H44]  50.29 54.34 180 top
Q5701  2N7002K-2-GP  [SOT23DGS2D4H44]  27.03 75.47 90 bottom
Q5702  2N7002KDW-GP  [SOT-363H44]  20.29 74.31 90 bottom
Q5703  LMBT3904LT1G-GP  [SOT23CBE2D4H44]  21.31 79.56 180 bottom
Q6101  2N7002KDW-GP  [SOT-363H44]  50.47 64.6 270 top
Q6201  2N7002KDW-GP  [SOT-363H44]  88.14 105.14 90 top
Q6301  2N7002K-2-GP  [SOT23DGS2D4H44]  76.07 102.98 270 top
Q6401  2N7002K-2-GP  [SOT23DGS2D4H44]  198.5 14.34 180 bottom
Q6403  LMUN2132LT1G-GP  [SOT23CBE2D4H44]  208.53 6.21 90 top
Q6404  LMUN2132LT1G-GP  [SOT23CBE2D4H44]  204.72 6.21 90 top
Q6405  LMUN2132LT1G-GP  [SOT23CBE2D4H44]  204.72 9.76 90 top
Q6406  2N7002KDW-GP  [SOT-363H44]  199.14 19.04 180 bottom
Q6407  2N7002K-2-GP  [SOT23DGS2D4H44]  208.53 9.76 90 top
Q6501  AO3404AL-GP  [SOT23DGS2D8H50]  188.47 57.26 270 top
Q6502  LMUN2132LT1G-GP  [SOT23CBE2D4H44]  173.1 43.67 270 top
Q6503  2N7002KDW-GP  [SOT-363H44]  130.81 7.73 180 bottom
Q6504  DMP2130L-7-GP  [SOT23DGS2D4H48]  194.56 19.92 270 bottom
Q6505  2N7002K-2-GP  [SOT23DGS2D4H44]  194.56 14.84 0 bottom
Q6701  2N7002KDW-GP  [SOT-363H44]  112.6 5.73 270 top
Q7901  2N7002KDW-GP  [SOT-363H44]  179.83 69.3 270 top
Q7902  2N7002K-2-GP  [SOT23DGS2D4H44]  187.45 82.66 180 top
Q7903  2N7002K-2-GP  [SOT23DGS2D4H44]  174.37 69.05 0 top
Q9101  2N7002K-2-GP  [SOT23DGS2D4H44]  240.28 30.34 270 top
Q9102  DMP2130L-7-GP  [SOT23DGS2D4H48]  255.14 30.47 90 top
Q9103  2N7002K-2-GP  [SOT23DGS2D4H44]  71.35 4.99 270 bottom
Q9104  2N7002K-2-GP  [SOT23DGS2D4H44]  255.14 26.78 90 top
R401  1KR2J-1-GP  [R402H16]  87.5 91.68 90 bottom
R402  51R2J-2-GP  [R402H16]  81.53 101.08 180 top
R403  499R2F-2-GP  [R402H16]  87.12 90.28 180 bottom
R404  0R0402-PAD-2-GP  [0R0402-PAD-1]  87.07 93.08 180 bottom
R405  10KR2J-3-GP  [R402H16]  84.96 87.49 180 bottom
R406  51R2J-2-GP  [R402H16]  82.42 101.08 180 top
R407  51R2J-2-GP  [R402H16]  86.31 103.11 270 top
R408  51R2J-2-GP  [R402H16]  82.93 102.86 0 top
R409  100R2J-2-GP  [R402H14]  84.33 102.86 0 top
R410  0R2J-2-GP  [R402H16]  140.46 50.66 270 bottom
R411  100KR2J-1-GP  [R402H16]  141.86 51.04 0 bottom
R414  100KR2J-1-GP  [R402H16]  141.86 52.82 180 bottom
R416  51R2J-2-GP  [R402H16]  81.41 102.86 0 top
R417  1KR2J-1-GP  [R402H16]  79.88 102.86 0 top
R419  1KR2J-1-GP  [R402H16]  92.68 94.42 0 bottom
R421  51R2J-2-GP  [R402H16]  84.33 101.08 180 top
R422  51R2J-2-GP  [R402H16]  78.87 104.13 90 top
R423  100R2J-2-GP  [R402H14]  83.31 101.08 180 top
R501  121R2F-GP  [R402H16]  119.99 65.39 0 top
R502  80D6R2F-L-GP  [R402H16]  120.88 65.39 0 top
R503  100R2F-L1-GP-U  [R402H14]  122.38 65.57 0 top
R504  0R0402-PAD-2-GP  [0R0402-PAD-1]  147.19 56.75 0 top
R505  470R2F-GP  [R402H16]  146.3 56.75 180 top
R506  220KR2F-GP  [R402H16]  74.8 52.06 180 top
R507  10KR2J-3-GP  [R402H16]  76.07 50.4 90 top
R601  49D9R2F-GP  [R402H16]  95.76 81.52 0 top
R602  0R0402-PAD-2-GP  [0R0402-PAD-1]  85.72 62.47 90 bottom
R603  100KR2J-1-GP  [R402H16]  93.09 90.31 0 bottom
R604  1KR2J-1-GP  [R402H16]  83.19 87.49 180 bottom
R605  1KR2J-1-GP  [R402H16]  85.47 84.69 90 bottom
R703  0R0603-PAD-2-GP-U  [0R0603-PAD-1-U]  119.81 86.32 270 top
R705  0R0603-PAD-2-GP-U  [0R0603-PAD-1-U]  105.13 65.72 180 top
R709  0R0402-PAD-2-GP  [0R0402-PAD-1]  93.57 92.06 0 bottom
R719  100R2F-L1-GP-U  [R402H14]  112.39 84.06 180 top
R720  100R2F-L1-GP-U  [R402H14]  115.19 84.19 0 top
R721  100R2F-L1-GP-U  [R402H14]  85.34 81.01 270 bottom
R722  100R2F-L1-GP-U  [R402H14]  85.34 80.12 90 bottom
R723  54D9R2F-L1-GP  [R402H16]  94.61 93.97 270 bottom
R726  100R2F-L1-GP-U  [R402H14]  93.93 90.33 180 bottom
R727  56R2J-4-GP  [R402H16]  94.58 92.22 180 bottom
R728  220R2J-L2-GP  [R402H16]  94.92 90.41 180 bottom
R732  0R0402-PAD-2-GP  [0R0402-PAD-1]  95.43 92.22 0 bottom
R734  100R2F-L1-GP-U  [R402H14]  119 82.92 180 top
R735  100R2F-L1-GP-U  [R402H14]  116.97 83.68 90 top
R801  24D9R2F-L-GP  [R402H16]  104.39 82.14 270 top
R802  10KR2J-3-GP  [R402H16]  139.32 81.65 270 bottom
R803  2K2R2J-2-GP  [R402H16]  139.32 80.5 90 bottom
R804  2K2R2J-2-GP  [R402H16]  137.54 80.76 90 bottom
R805  0R0402-PAD-2-GP  [0R0402-PAD-1]  129.57 81.37 180 top
R806  100KR2J-1-GP  [R402H16]  127.18 80.99 270 top
R1101  0R0603-PAD-2-GP-U  [0R0603-PAD-1-U]  121.54 80.91 270 top
R1102  0R0603-PAD-2-GP-U  [0R0603-PAD-1-U]  145.8 84.62 270 top
R1106  0R0805-PAD-2-GP-U  [0R0805-PAD-1-U]  147.7 81.27 90 bottom
R1112  0R0603-PAD-2-GP-U  [0R0603-PAD-1-U]  146.94 71.23 90 bottom
R1117  0R1206-PAD-1-GP  [0R1206-PAD-1]  148.08 86.98 0 top
R1118  0R0603-PAD-2-GP-U  [0R0603-PAD-1-U]  144.86 87.31 270 top
R1139  0R0603-PAD-2-GP-U  [0R0603-PAD-1-U]  158.09 60.06 0 bottom
R1204  10KR2F-L1-GP  [R402H15]  113.87 8.52 0 top
R1205  0R0402-PAD-2-GP  [0R0402-PAD-1]  112.98 8.52 180 top
R1206  2R2F-GP  [R402H16]  86.36 11.42 0 top
R1208  10KR2F-L1-GP  [R402H15]  114.76 8.52 0 top
R1209  24D9R2F-L-GP  [R402H16]  89.33 9.41 270 bottom
R1210  0R0402-PAD-2-GP  [0R0402-PAD-1]  115.65 8.52 180 top
R1211  10KR2F-L1-GP  [R402H15]  89.52 11.2 90 top
R1212  0R0402-PAD-2-GP  [0R0402-PAD-1]  88.25 11.58 0 top
R1215  240R2F-1-GP  [R402H16]  77.98 11.16 0 top
R1216  SC2D2U10V3KX-L-GP  [C603H36]  116.44 17.5 180 top
R1302  10KR2F-L1-GP  [R402H15]  189.87 11.16 180 top
R1303  0R0402-PAD-2-GP  [0R0402-PAD-1]  188.98 11.16 0 top
R1305  2R2F-GP  [R402H16]  86.23 56.75 270 bottom
R1306  10KR2F-L1-GP  [R402H15]  190.25 9.13 270 bottom
R1307  0R2J-L-GP  [R402H15]  189.74 7.86 180 bottom
R1309  24D9R2F-L-GP  [R402H16]  86.61 55.36 180 bottom
R1310  10KR2F-L1-GP  [R402H15]  163.86 11.42 0 top
R1311  0R0402-PAD-2-GP  [0R0402-PAD-1]  162.99 11.31 180 top
R1312  240R2F-1-GP  [R402H16]  155.47 13.78 270 top
R1501  100R2F-L1-GP-U  [R402H14]  126.36 85.71 180 top
R1502  200R2F-L-GP  [R402H16]  131.7 68.74 180 top
R1503  0R0402-PAD-2-GP  [0R0402-PAD-1]  129.67 87.36 180 top
R1504  10KR2J-3-GP  [R402H16]  117.73 51.29 180 top
R1601  0R0402-PAD-2-GP  [0R0402-PAD-1]  143.51 62.91 180 bottom
R1602  0R0402-PAD-2-GP  [0R0402-PAD-1]  142.62 62.91 180 bottom
R1603  113R2F-GP  [R402H16]  128.65 75.8 270 top
R1604  100R2F-L1-GP-U  [R402H14]  129.41 83.55 180 top
R1608  10KR2J-3-GP  [R402H16]  136.91 84.44 90 bottom
R1609  10KR2J-3-GP  [R402H16]  195.81 10.02 180 top
R1610  10KR2J-3-GP  [R402H16]  135.57 88.89 90 bottom
R1701  10KR2J-3-GP  [R402H16]  134.11 91.68 180 bottom
R1702  1KR2J-1-GP  [R402H16]  152.15 69.33 90 bottom
R1703  0R0402-PAD-2-GP  [0R0402-PAD-1]  155.57 65.83 180 top
R1704  0R2J-2-GP  [R402H16]  120.9 51.17 90 bottom
R1705  0R0402-PAD-2-GP  [0R0402-PAD-1]  149.86 64.63 270 top
R1706  0R0402-PAD-2-GP  [0R0402-PAD-1]  119.2 50.23 90 bottom
R1707  10KR2J-3-GP  [R402H16]  148.34 60.95 180 top
R1708  0R2J-2-GP  [R402H16]  153.49 68.26 180 top
R1709  0R2J-2-GP  [R402H16]  123.06 57.52 180 bottom
R1710  0R2J-2-GP  [R402H16]  124.08 57.52 180 bottom
R1711  0R0603-PAD-2-GP-U  [0R0603-PAD-1-U]  149.61 61.96 0 top
R1712  0R0402-PAD-2-GP  [0R0402-PAD-1]  154.69 65.83 180 top
R1713  0R0402-PAD-2-GP  [0R0402-PAD-1]  152.78 74.79 180 bottom
R1714  10KR2J-3-GP  [R402H16]  149.86 63.74 90 top
R1715  100KR2J-1-GP  [R402H16]  155.45 74.79 180 bottom
R1716  100KR2F-L1-GP  [R402H16]  90.04 92.44 270 bottom
R1717  10KR2J-3-GP  [R402H16]  131.32 92.64 0 bottom
R1718  0R2J-2-GP  [R402H16]  120.9 50.28 270 bottom
R1719  47KR2F-GP  [R402H16]  91.82 90.75 270 bottom
R1720  0R2J-2-GP  [R402H16]  158.12 72.12 270 bottom
R1721  0R2J-2-GP  [R402H16]  46.84 63.74 180 top
R1722  100KR2J-4-GP  [R402H15]  90.04 91.55 270 bottom
R1724  0R0805-PAD-2-GP-U  [0R0805-PAD-1-U]  152.78 79.97 0 bottom
R1726  10KR2J-3-GP  [R402H16]  156.08 66.66 90 bottom
R1727  100KR2J-1-GP  [R402H16]  152.27 67.17 0 bottom
R1728  0R2J-2-GP  [R402H16]  150.5 66.53 180 bottom
R1729  0R0402-PAD-2-GP  [0R0402-PAD-1]  149.61 66.53 180 bottom
R1730  1MR2J-1-GP  [R402H16]  125.22 54.06 270 top
R1731  20KR2J-L2-GP  [R402H16]  126.26 72.81 0 top
R1732  10KR2F-2-GP  [R402H16]  119.2 51.12 90 bottom
R1734  60D4R2F-GP  [R402H16]  90.04 90.66 90 bottom
R1735  0R0805-PAD-2-GP-U  [0R0805-PAD-1-U]  150.88 79.97 0 bottom
R1736  0R0402-PAD-2-GP  [0R0402-PAD-1]  147.45 60.95 180 top
R1737  100KR2J-1-GP  [R402H16]  152.65 71.59 270 bottom
R1801  0R0402-PAD-2-GP  [0R0402-PAD-1]  132.28 51.55 270 bottom
R1802  1MR2J-1-GP  [R402H16]  112.78 91.93 270 bottom
R1803  2K7R2F-GP  [R402H16]  108.71 90.16 90 bottom
R1804  22R2J-2-GP  [R402H16]  130.94 56.35 180 bottom
R1805  22R2J-2-GP  [R402H16]  131.78 56.35 180 bottom
R1810  0R0402-PAD-2-GP  [0R0402-PAD-1]  112.78 92.82 270 bottom
R1811  10R2F-L-GP  [R402H14]  144.98 67.22 0 bottom
R1812  0R0402-PAD-2-GP  [0R0402-PAD-1]  135.59 70.5 90 bottom
R1813  0R2J-2-GP  [R402H16]  122.56 53.71 180 bottom
R1814  10KR2J-3-GP  [R402H16]  145.92 58.02 270 top
R1815  10MR2J-L-GP  [R402H16]  134.29 57.14 180 bottom
R1816  0R0402-PAD-2-GP  [0R0402-PAD-1]  135.64 68.57 90 bottom
R1817  0R2J-2-GP  [R402H16]  124.26 53.58 180 bottom
R1818  8K2R2F-1-GP  [R402H16]  140.21 51.42 90 top
R1819  0R0402-PAD-2-GP  [0R0402-PAD-1]  140.21 52.31 90 top
R1820  150KR2F-L-GP  [R402H16]  131.44 72.12 270 top
R1821  2K2R2J-2-GP  [R402H16]  145.49 77.38 90 top
R1822  1KR2J-1-GP  [R402H16]  146.81 75.55 270 top
R1823  1KR2J-1-GP  [R402H16]  145.29 75.17 0 top
R1824  1KR2J-1-GP  [R402H16]  136.96 67.12 0 bottom
R1825  1KR2J-1-GP  [R402H16]  135.23 67.14 180 bottom
R1826  1KR2J-1-GP  [R402H16]  136.08 67.14 0 bottom
R1827  1KR2J-1-GP  [R402H16]  144.65 64.12 0 bottom
R1828  0R2J-2-GP  [R402H16]  136.7 69.4 90 bottom
R1837  10KR2J-3-GP  [R402H16]  141.86 45.96 180 top
R1838  10KR2J-3-GP  [R402H16]  127.07 53.3 0 bottom
R1901  200R2F-L-GP  [R402H16]  125.22 74.92 180 top
R1904  100KR2J-1-GP  [R402H16]  129.44 91.55 180 bottom
R1908  0R0402-PAD-2-GP  [0R0402-PAD-1]  117.22 51.55 0 bottom
R1909  1KR2J-1-GP  [R402H16]  116.36 51.57 0 bottom
R2002  10KR2J-3-GP  [R402H16]  142.24 76.57 90 bottom
R2005  10KR2J-3-GP  [R402H16]  143.51 76.06 180 bottom
R2006  1KR2J-1-GP  [R402H16]  140.21 50.53 270 top
R2007  1KR2J-1-GP  [R402H16]  148.46 68.82 90 bottom
R2008  10KR2J-3-GP  [R402H16]  142.24 75.42 270 bottom
R2017  10KR2J-3-GP  [R402H16]  146.18 58.9 270 top
R2018  10KR2J-3-GP  [R402H16]  146.18 59.79 90 top
R2019  1KR2J-1-GP  [R402H16]  146.43 69.33 0 bottom
R2023  10KR2J-3-GP  [R402H16]  152.07 69.33 270 top
R2024  10KR2J-3-GP  [R402H16]  152.07 70.22 90 top
R2039  10KR2J-3-GP  [R402H16]  153.03 65.9 0 top
R2046  51KR2J-1-GP  [R402H16]  141.6 80.76 90 bottom
R2048  51KR2J-1-GP  [R402H16]  131.44 74.15 270 top
R2049  51KR2J-1-GP  [R402H16]  131.44 73.26 270 top
R2050  10KR2J-3-GP  [R402H16]  130.94 70.47 0 top
R2051  10KR2J-3-GP  [R402H16]  71.83 91.04 0 bottom
R2052  10KR2J-3-GP  [R402H16]  49.28 88.38 90 bottom
R2101  0R0402-PAD-2-GP  [0R0402-PAD-1]  121.56 72.17 180 top
R2106  0R0603-PAD-2-GP-U  [0R0603-PAD-1-U]  126.01 53.07 0 bottom
R2107  0R0603-PAD-2-GP-U  [0R0603-PAD-1-U]  140.59 87.87 90 bottom
R2108  0R0603-PAD-2-GP-U  [0R0603-PAD-1-U]  138.18 86.47 90 bottom
R2109  0R0603-PAD-2-GP-U  [0R0603-PAD-1-U]  138.18 88.25 90 bottom
R2110  0R3J-0-U-GP  [R603H22]  140.59 85.58 90 bottom
R2111  0R3J-0-U-GP  [R603H22]  146.35 83.3 90 top
R2401  10KR2F-2-GP  [R402H16]  141.6 51.93 0 top
R2402  0R2J-2-GP  [R402H16]  158.22 78.06 270 bottom
R2410  0R0402-PAD-2-GP  [0R0402-PAD-1]  204.47 40.63 180 top
R2411  0R0402-PAD-2-GP  [0R0402-PAD-1]  199.26 42.66 180 top
R2412  0R0402-PAD-2-GP  [0R0402-PAD-1]  218.87 25.77 0 bottom
R2413  100KR2J-1-GP  [R402H16]  91.19 108.62 270 top
R2414  4K7R2J-2-GP  [R402H16]  278.38 40.63 90 bottom
R2415  10KR2J-3-GP  [R402H16]  201.17 20.81 180 bottom
R2416  0R0402-PAD-2-GP  [0R0402-PAD-1]  204.98 26.27 180 bottom
R2417  100KR2J-1-GP  [R402H16]  201.93 26.66 90 bottom
R2418  0R2J-2-GP  [R402H16]  203.71 26.66 270 bottom
R2419  0R2J-2-GP  [R402H16]  35.69 71.87 0 bottom
R2420  0R2J-2-GP  [R402H16]  102.11 6.97 90 top
R2421  330R2J-3-GP  [R402H16]  208.28 18.78 180 top
R2422  0R2J-2-GP  [R402H16]  71.81 71.31 180 top
R2423  330R2J-3-GP  [R402H16]  201.24 9.61 0 bottom
R2425  330R2J-3-GP  [R402H16]  205.49 16.62 90 top
R2426  0R2J-2-GP  [R402H16]  216.41 34.02 270 bottom
R2427  0R0402-PAD-2-GP  [0R0402-PAD-1]  210.85 34.4 180 bottom
R2428  0R2J-2-GP  [R402H16]  208.03 15.73 90 top
R2429  10KR2J-3-GP  [R402H16]  210.95 46.47 180 top
R2430  10KR2J-3-GP  [R402H16]  215.65 39.99 180 top
R2431  0R0402-PAD-2-GP  [0R0402-PAD-1]  216.66 39.99 180 top
R2432  1KR2J-1-GP  [R402H16]  217.68 19.04 180 top
R2434  100KR2J-1-GP  [R402H16]  274.32 25.39 270 bottom
R2435  0R0402-PAD-2-GP  [0R0402-PAD-1]  198.12 24.5 90 bottom
R2436  100KR2J-1-GP  [R402H16]  198.12 25.39 90 bottom
R2437  43R2J-GP  [R402H16]  201.04 24.5 0 bottom
R2438  10KR2J-3-GP  [R402H16]  208.74 34.76 270 bottom
R2439  0R0402-PAD-2-GP  [0R0402-PAD-1]  198.12 23.61 270 bottom
R2440  0R2J-2-GP  [R402H16]  129.79 96.63 270 bottom
R2441  100KR2F-L1-GP  [R402H16]  203.71 18.4 90 top
R2442  64K9R2F-1-GP  [R402H16]  202.36 16.27 180 top
R2443  10KR2F-2-GP  [R402H16]  201.24 15.56 0 top
R2444  100KR2F-L1-GP  [R402H16]  202.08 13.78 0 top
R2445  0R0402-PAD-2-GP  [0R0402-PAD-1]  200.41 11.42 180 bottom
R2446  0R0603-PAD-2-GP-U  [0R0603-PAD-1-U]  209.68 43.04 90 top
R2447  10KR2J-3-GP  [R402H16]  25.91 60.31 90 bottom
R2449  100KR2J-1-GP  [R402H16]  202.59 34.66 90 bottom
R2450  100KR2J-1-GP  [R402H16]  201.32 35.04 0 bottom
R2451  100KR2J-1-GP  [R402H16]  215.95 19.04 0 top
R2452  100KR2J-1-GP  [R402H16]  215.11 19.04 0 top
R2453  10KR2J-3-GP  [R402H16]  208.03 40.12 180 top
R2454  100KR2J-1-GP  [R402H16]  211.46 18.4 270 top
R2455  1KR2J-1-GP  [R402H16]  102.11 6.08 90 top
R2456  1KR2J-1-GP  [R402H16]  92.13 4.89 90 top
R2457  0R2J-2-GP  [R402H16]  213.11 38.09 0 bottom
R2458  0R0402-PAD-2-GP  [0R0402-PAD-1]  208.03 14.84 270 top
R2459  0R2J-2-GP  [R402H16]  214.88 38.09 180 bottom
R2460  0R2J-2-GP  [R402H16]  214 38.09 180 bottom
R2461  100KR2J-1-GP  [R402H16]  228.35 10.4 90 top
R2462  0R0402-PAD-2-GP  [0R0402-PAD-1]  210.92 42.02 0 bottom
R2463  0R2J-2-GP  [R402H16]  278.26 43.42 270 top
R2464  0R2J-2-GP  [R402H16]  278.26 42.53 270 top
R2465  0R2J-2-GP  [R402H16]  278.38 41.51 90 bottom
R2466  0R2J-2-GP  [R402H16]  278.38 42.4 90 bottom
R2467  1KR2J-1-GP  [R402H16]  211.46 19.29 90 top
R2469  0R0402-PAD-2-GP  [0R0402-PAD-1]  218.57 21.07 180 top
R2471  0R0402-PAD-2-GP  [0R0402-PAD-1]  68.96 71.74 180 top
R2472  0R2J-2-GP  [R402H16]  226.01 5.78 270 bottom
R2473  0R0402-PAD-2-GP  [0R0402-PAD-1]  226.01 6.67 270 bottom
R2474  0R0402-PAD-2-GP  [0R0402-PAD-1]  68.15 71.74 180 top
R2476  0R2J-2-GP  [R402H16]  280.16 44.82 90 bottom
R2478  100KR2J-1-GP  [R402H16]  277.11 41.13 180 bottom
R2479  0R0402-PAD-2-GP  [0R0402-PAD-1]  228.35 11.29 90 top
R2480  0R2J-2-GP  [R402H16]  195.91 26.27 90 bottom
R2481  0R0402-PAD-2-GP  [0R0402-PAD-1]  207.14 40.12 180 top
R2482  0R2J-2-GP  [R402H16]  222.12 5.45 0 top
R2483  0R2J-2-GP  [R402H16]  223.01 5.45 0 top
R2490  0R0402-PAD-2-GP  [0R0402-PAD-1]  214.63 34.02 90 bottom
R2491  0R0402-PAD-2-GP  [0R0402-PAD-1]  220.6 7.73 180 bottom
R2492  0R2J-2-GP  [R402H16]  130.68 97.52 270 bottom
R2496  100KR2J-1-GP  [R402H16]  204.09 31.35 270 bottom
R2497  0R2J-2-GP  [R402H16]  205.49 15.73 90 top
R2498  0R0402-PAD-2-GP  [0R0402-PAD-1]  91.19 109.43 270 top
R2499  100KR2J-1-GP  [R402H16]  208.74 33.92 270 bottom
R2501  4K7R2J-2-GP  [R402H16]  154.91 61.43 90 bottom
R2502  1KR2J-1-GP  [R402H16]  230.12 43.93 180 bottom
R2503  10R2F-L-GP  [R402H14]  146.81 61.71 0 bottom
R2504  10MR2J-L-GP  [R402H16]  228.85 44.44 90 bottom
R2509  10R2F-L-GP  [R402H14]  158.62 50.28 90 bottom
R2511  10R2F-L-GP  [R402H14]  158.62 49.39 90 bottom
R2512  10R2F-L-GP  [R402H14]  170.31 46.72 270 bottom
R2513  10R2F-L-GP  [R402H14]  171.35 49.67 90 bottom
R2514  10R2F-L-GP  [R402H14]  171.32 48.8 90 bottom
R2515  4K7R2J-2-GP  [R402H16]  170.03 52.03 0 bottom
R2518  4K7R2J-2-GP  [R402H16]  91.49 8.44 270 top
R2519  10R2F-L-GP  [R402H14]  99.44 6.59 270 bottom
R2521  10R2F-L-GP  [R402H14]  99.44 5.7 270 bottom
R2522  10R2F-L-GP  [R402H14]  99.44 4.81 90 bottom
R2601  0R0402-PAD-2-GP  [0R0402-PAD-1]  78.38 88.76 0 bottom
R2602  0R2J-2-GP  [R402H16]  77.98 87.49 270 bottom
R2603  14KR2F-GP  [R402H16]  72.26 93.84 270 bottom
R2604  2KR2F-3-GP  [R402H16]  77.55 88.76 0 bottom
R2605  0R2J-2-GP  [R402H16]  207.26 51.93 180 bottom
R2606  0R0402-PAD-2-GP  [0R0402-PAD-1]  214.5 44.31 90 top
R2607  10KR2J-3-GP  [R402H16]  76.33 86.4 0 bottom
R2612  0R2J-2-GP  [R402H16]  75.49 86.4 0 bottom
R2616  14KR2F-GP  [R402H16]  201.04 108.32 0 bottom
R2617  10K5R2F-GP  [R402H16]  206.32 108.24 0 bottom
R2618  0R0402-PAD-2-GP  [0R0402-PAD-1]  207.17 108.21 180 bottom
R2702  0R0805-PAD-2-GP-U  [0R0805-PAD-1-U]  30.61 19.04 0 top
R2703  0R0603-PAD-2-GP-U  [0R0603-PAD-1-U]  16.41 16.47 180 top
R2704  0R0805-PAD-2-GP-U  [0R0805-PAD-1-U]  28.7 19.8 0 top
R2706  0R0603-PAD-2-GP-U  [0R0603-PAD-1-U]  32 3.39 90 top
R2707  20KR2F-L-GP  [R402H16]  18.19 14.69 270 top
R2708  0R0402-PAD-2-GP  [0R0402-PAD-1]  27.3 13.96 90 bottom
R2709  200KR2F-L-GP  [R402H16]  21.46 17.05 90 top
R2711  100KR2J-1-GP  [R402H16]  20.45 5.7 180 top
R2712  0R0402-PAD-2-GP  [0R0402-PAD-1]  17.48 16.8 180 top
R2713  0R0402-PAD-2-GP  [0R0402-PAD-1]  32.38 7.86 180 top
R2714  0R0402-PAD-2-GP  [0R0402-PAD-1]  26.8 17.77 0 top
R2715  10KR2J-3-GP  [R402H16]  42.31 4.6 0 bottom
R2716  100R2J-2-GP  [R402H14]  25.91 17.77 0 top
R2717  2K2R2J-2-GP  [R402H16]  20.42 15.35 180 bottom
R2718  0R0402-PAD-2-GP  [0R0402-PAD-1]  22.12 21.55 90 top
R2719  0R0402-PAD-2-GP  [0R0402-PAD-1]  24.99 18.15 0 top
R2720  0R0402-PAD-2-GP  [0R0402-PAD-1]  24.16 18.15 0 top
R2721  0R2J-2-GP  [R402H16]  28.98 15.96 180 bottom
R2722  100KR2J-1-GP  [R402H16]  20.27 18.07 90 top
R2723  0R0402-PAD-2-GP  [0R0402-PAD-1]  20.19 14.08 90 bottom
R2724  0R2J-2-GP  [R402H16]  27.23 15.53 270 bottom
R2726  0R0402-PAD-2-GP  [0R0402-PAD-1]  29.21 5.96 270 top
R2727  0R0603-PAD-2-GP-U  [0R0603-PAD-1-U]  32.26 6.36 90 top
R2728  0R0402-PAD-2-GP  [0R0402-PAD-1]  42.97 7.95 90 bottom
R2729  0R2J-2-GP  [R402H16]  42.97 7.06 90 bottom
R2730  0R0603-PAD-2-GP-U  [0R0603-PAD-1-U]  18.54 16.5 180 top
R2731  0R0603-PAD-2-GP-U  [0R0603-PAD-1-U]  19.56 19.67 0 top
R2733  4K7R2J-2-GP  [R402H16]  43.24 6.12 270 bottom
R2901  0R0402-PAD-2-GP  [0R0402-PAD-1]  15.27 16.11 0 top
R2906  0R0603-PAD-2-GP-U  [0R0603-PAD-1-U]  16.31 2.93 270 top
R2907  0R0603-PAD-2-GP-U  [0R0603-PAD-1-U]  20.19 2.78 90 bottom
R2908  16D5R2F-GP  [R402H16]  24.49 3.82 270 top
R2909  0R0603-PAD-2-GP-U  [0R0603-PAD-1-U]  15.47 12.38 180 top
R2910  16D5R2F-GP  [R402H16]  25.53 5.45 180 bottom
R2911  0R0603-PAD-2-GP-U  [0R0603-PAD-1-U]  16.31 4.25 270 top
R2912  4K7R2J-2-GP  [R402H16]  24.2 5.08 0 top
R2913  4K7R2J-2-GP  [R402H16]  23.51 3.55 180 bottom
R2919  10KR2J-3-GP  [R402H16]  24.49 2.96 90 top
R2920  10KR2J-3-GP  [R402H16]  15.75 9.51 90 top
R2921  1KR2J-1-GP  [R402H16]  15.98 8.49 270 top
R2922  1KR2J-1-GP  [R402H16]  15.98 7.35 270 top
R2923  0R0603-PAD-2-GP-U  [0R0603-PAD-1-U]  20.85 19.67 0 top
R3103  0R0603-PAD-2-GP-U  [0R0603-PAD-1-U]  49.81 91.55 90 bottom
R3104  0R0402-PAD-2-GP  [0R0402-PAD-1]  49.15 89.22 270 bottom
R3105  15KR2J-1-GP  [R402H16]  48.9 94.85 270 bottom
R3106  10KR2J-3-GP  [R402H16]  48.9 93.97 270 bottom
R3107  1KR2J-1-GP  [R402H16]  49.81 95.69 90 bottom
R3108  2K49R2F-GP  [R402H16]  41.66 91.04 180 bottom
R3109  10KR2J-3-GP  [R402H16]  34.34 96.33 180 top
R3110  20KR2J-L2-GP  [R402H16]  34.8 97.65 90 top
R3111  100KR2J-1-GP  [R402H16]  31.83 94.04 90 top
R3112  0R0402-PAD-2-GP  [0R0402-PAD-1]  54.61 96.12 90 bottom
R3113  0R0402-PAD-2-GP  [0R0402-PAD-1]  50.04 96.89 270 top
R3401  100KR2J-1-GP  [R402H16]  21.84 52.56 0 top
R3404  22K1R2F-L-GP  [R402H16]  26.92 54.6 0 bottom
R3405  10KR2J-3-GP  [R402H16]  29.72 58.25 270 top
R3501  100KR2J-1-GP  [R402H16]  20.83 29.2 0 top
R3502  100KR2J-1-GP  [R402H16]  278 33.51 90 bottom
R3605  0R0402-PAD-2-GP  [0R0402-PAD-1]  20.57 53.45 90 bottom
R3606  0R0402-PAD-2-GP  [0R0402-PAD-1]  20.57 52.44 90 bottom
R3607  0R0402-PAD-2-GP  [0R0402-PAD-1]  20.57 51.29 90 bottom
R3608  0R0402-PAD-2-GP  [0R0402-PAD-1]  20.57 50.4 90 bottom
R3609  0R0402-PAD-2-GP  [0R0402-PAD-1]  21.72 25.89 90 bottom
R3610  0R0402-PAD-2-GP  [0R0402-PAD-1]  21.72 24.88 90 bottom
R3611  0R0402-PAD-2-GP  [0R0402-PAD-1]  21.72 23.61 90 bottom
R3612  0R0402-PAD-2-GP  [0R0402-PAD-1]  21.72 22.59 90 bottom
